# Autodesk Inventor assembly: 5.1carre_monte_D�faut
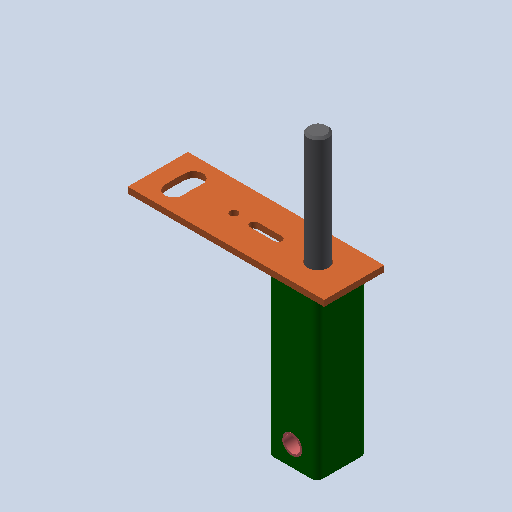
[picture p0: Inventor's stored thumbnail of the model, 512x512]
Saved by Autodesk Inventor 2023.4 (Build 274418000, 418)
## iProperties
Created: 2011-01
Part Number: 5.1carre_monte_D�faut
Document SubType Name: Assembly
Designer: eric
Mass: 25.3714 g
Surface Area: 253.737 cm^2
Volume: 25.3714 cm^3
Density: 1 g/cm^3
Author: eric
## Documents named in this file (9)
- C:\Users\bruno\Documents\1-Cours-2024-25\TSsI\7-Dynamique\chariot de golf\chariot_de_golf\chariot_de_golf_trolem\5.1carre_monte_Defaut.iam
- C:\Users\bruno\Documents\1-Cours-2024-25\TSsI\7-Dynamique\chariot de golf\chariot_de_golf\chariot_de_golf_trolem\bead103_Defaut.ipt
- C:\Users\bruno\Documents\1-Cours-2024-25\TSsI\7-Dynamique\chariot de golf\chariot_de_golf\chariot_de_golf_trolem\5.1entretoise_Defaut.ipt
- C:\Users\bruno\Documents\1-Cours-2024-25\TSsI\7-Dynamique\chariot de golf\chariot_de_golf\chariot_de_golf_trolem\5.1plaque_Defaut.ipt
- C:\Users\bruno\Documents\1-Cours-2024-25\TSsI\7-Dynamique\chariot de golf\chariot_de_golf\chariot_de_golf_trolem\5.1VisH M10-60_Defaut.ipt
- C:\Users\bruno\Documents\1-Cours-2024-25\TSsI\7-Dynamique\chariot de golf\chariot_de_golf\chariot_de_golf_trolem\5.1TubeCarre25x25x1.5_Defaut.ipt
- C:\Users\bruno\Documents\1-Cours-2024-25\TSsI\7-Dynamique\chariot de golf\chariot_de_golf\chariot_de_golf_trolem\bead106_Defaut.ipt
- C:\Users\bruno\Documents\1-Cours-2024-25\TSsI\7-Dynamique\chariot de golf\chariot_de_golf\chariot_de_golf_trolem\bead104_Defaut.ipt
- C:\Users\bruno\Documents\1-Cours-2024-25\TSsI\7-Dynamique\chariot de golf\chariot_de_golf\chariot_de_golf_trolem\bead105_Defaut.ipt
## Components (8 placed, 8 different names)
1. bead103_Defaut:1
2. 5.1entretoise_Defaut:1
3. 5.1plaque_Defaut:1
4. 5.1VisH M10-60_Defaut:1
5. 5.1TubeCarre25x25x1.5_Defaut:1
6. bead106_Defaut:1
7. bead104_Defaut:1
8. bead105_Defaut:1
